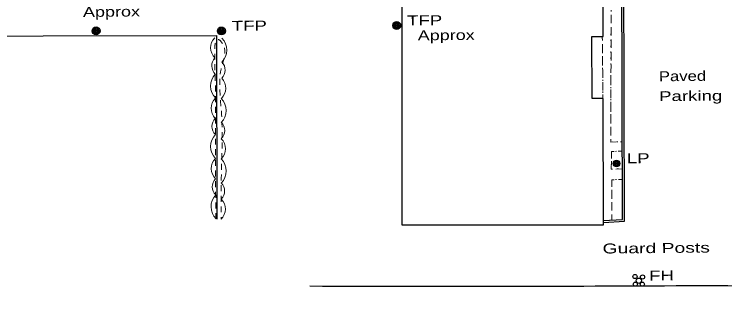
# Model space of a CAD drawing. Extents: x 2362213 to 2366494, y 6968794 to 6978110.
# Drawn here: x 2363722.2 to 2364064.6, y 6975816.2 to 6975952.7 of the extents above; entities that cross this region are included whole.
import ezdxf

# ---------------------------------------------------------------- set-up
doc = ezdxf.new("R2010")
doc.units = 0
doc.header["$LTSCALE"] = 1.9
for name, pattern in [('DASH_DOUBLE_DOT', [9.2, 5, -1.2, 0.3, -1.2, 0.3, -1.2]), ('DOTTED', [1.5, 0.3, -1.2]), ('SHORT_DASHED', [2.7, 1.5, -1.2])]:
    doc.linetypes.add(name, pattern=pattern)
for name, color, linetype, lineweight in [('11', 7, 'Continuous', 25), ('13', 7, 'Continuous', 13), ('2', 7, 'Continuous', 25), ('20', 7, 'Continuous', 25), ('25', 7, 'Continuous', 25), ('29', 7, 'Continuous', 13), ('35', 7, 'Continuous', 13), ('7', 7, 'Continuous', 25)]:
    doc.layers.add(name, color=color, linetype=linetype, lineweight=lineweight)

msp = doc.modelspace()

# ---------------------------------------------------------------- linework, layer by layer
at = {"layer": '11'}
msp.add_lwpolyline([(2364005.429, 6976091.845), (2363908.886, 6976091.766), (2363909.079, 6975850.977), (2364006.102, 6975851.05), (2364006.053, 6975911.893), (2364000.643, 6975911.891), (2364000.637, 6975941.923), (2364005.977, 6975941.923), (2364005.966, 6976001.926), (2364000.315, 6976001.922), (2364000.291, 6976031.843), (2364005.441, 6976031.842)], close=True, dxfattribs=at)
msp.add_lwpolyline([(2363569.083, 6975884.661), (2363568.867, 6975941.911), (2363819.655, 6975942.339), (2363819.848, 6975853.777)], dxfattribs=at)
at = {"layer": '13'}
for p, q in [((2364009.808, 6975952.36), (2364009.806, 6975948.36)), ((2364009.805, 6975946.36), (2364009.803, 6975942.36)), ((2364005.636, 6975939.89), (2364005.607, 6975941.92)), ((2364009.802, 6975940.36), (2364009.8, 6975936.36)), ((2364005.694, 6975933.89), (2364005.655, 6975937.89)), ((2364009.799, 6975934.359), (2364009.797, 6975930.359)), ((2364005.761, 6975927.891), (2364005.713, 6975931.89)), ((2364009.796, 6975928.359), (2364009.794, 6975924.359)), ((2364005.828, 6975921.891), (2364005.78, 6975925.891)), ((2364005.885, 6975915.891), (2364005.847, 6975919.891)), ((2364009.794, 6975922.359), (2364009.782, 6975918.359)), ((2364009.781, 6975916.358), (2364009.769, 6975912.358)), ((2364005.923, 6975911.892), (2364005.904, 6975913.891)), ((2364009.768, 6975910.358), (2364009.756, 6975906.358)), ((2364009.755, 6975904.357), (2364009.753, 6975900.357)), ((2364009.752, 6975898.357), (2364009.74, 6975894.357)), ((2364014.323, 6975891.061), (2364015.303, 6975891.09)), ((2364015.316, 6975886.57), (2364013.316, 6975886.491)), ((2364012.108, 6975877.909), (2364015.337, 6975878.01)), ((2364015.356, 6975872.9), (2364013.356, 6975872.831)), ((2364010.202, 6975867.89), (2364010.22, 6975863.89)), ((2364010.229, 6975861.89), (2364010.237, 6975857.889)), ((2364010.246, 6975855.89), (2364010.251, 6975853.32))]:
    msp.add_line(p, q, dxfattribs=at)
at = {"layer": '13', "linetype": 'DOTTED'}
msp.add_line((2364005.923, 6975911.892), (2364005.607, 6975941.92), dxfattribs=at)
for points in [[(2364015.087, 6975963.101), (2364009.816, 6975963.091), (2364009.733, 6975890.947), (2364015.303, 6975891.09)], [(2364015.316, 6975886.57), (2364010.006, 6975886.359), (2364009.937, 6975877.838), (2364015.337, 6975878.01)], [(2364015.356, 6975872.9), (2364010.186, 6975872.72), (2364010.251, 6975853.32)]]:
    msp.add_lwpolyline(points, dxfattribs=at)
at = {"layer": '13'}
for points in [[(2364009.739, 6975892.357), (2364009.733, 6975890.947), (2364012.323, 6975891.012)], [(2364011.317, 6975886.412), (2364010.006, 6975886.359), (2364009.982, 6975883.669)], [(2364009.971, 6975881.668), (2364009.937, 6975877.838), (2364010.107, 6975877.84)], [(2364011.357, 6975872.762), (2364010.186, 6975872.72), (2364010.193, 6975869.89)]]:
    msp.add_lwpolyline(points, dxfattribs=at)
at = {"layer": '2'}
for points in [[(2364006.053, 6975853.1), (2364015.41, 6975853.579), (2364014.702, 6976094.903)], [(2364006.102, 6975852.141), (2364016.368, 6975852.668), (2364015.662, 6976094.903)]]:
    msp.add_lwpolyline(points, dxfattribs=at)
msp.add_spline([(2364107.921, 6975821.279), (2364052.236, 6975821.458), (2363963.325, 6975821.152), (2363864.629, 6975821.302)], degree=3, dxfattribs=at)
at = {"layer": '20'}
for centre, radius in [((2363906.543, 6975947.187), 1.9), ((2363906.543, 6975947.187), 1.442), ((2363906.543, 6975947.187), 0.973), ((2363906.543, 6975947.187), 0.539), ((2363906.543, 6975947.187), 0.192), ((2363761.69, 6975944.607), 1.9), ((2363761.69, 6975944.607), 1.442), ((2363761.69, 6975944.607), 0.973), ((2363761.69, 6975944.607), 0.539), ((2363761.69, 6975944.607), 0.192), ((2363822.073, 6975944.572), 1.9), ((2363822.073, 6975944.572), 1.442), ((2363822.073, 6975944.572), 0.973), ((2363822.073, 6975944.572), 0.539), ((2363822.073, 6975944.572), 0.192), ((2364012.451, 6975880.632), 1.6), ((2364012.451, 6975880.632), 1.3), ((2364012.451, 6975880.632), 1), ((2364012.451, 6975880.632), 0.539), ((2364012.451, 6975880.632), 0.192), ((2364023.201, 6975824.002), 1.3)]:
    msp.add_circle(centre, radius, dxfattribs=at)
at = {"layer": '25', "linetype": 'DASH_DOUBLE_DOT'}
msp.add_spline([(2364310.491, 6975656.319), (2364309.315, 6975672.72), (2364298.364, 6975726.467), (2364286.692, 6975764.268), (2364256.739, 6975841.117), (2364237.482, 6975880.675), (2364207.194, 6975936.919), (2364187.287, 6975969.191), (2364152.962, 6976013.656), (2364115.828, 6976058.935), (2364082.642, 6976102.511), (2364057.611, 6976141.394), (2364041.755, 6976162.894), (2364026.344, 6976185.928), (2364018.13, 6976197.872), (2364016.1, 6976205.372), (2364015.847, 6976210.94), (2364013.084, 6976216.455), (2364009.051, 6976219.846), (2363997.967, 6976222.231), (2363988.629, 6976226.282), (2363979.044, 6976231.97), (2363962.438, 6976249.274), (2363954.619, 6976263.83), (2363947.844, 6976280.085), (2363938.606, 6976306.129), (2363935.221, 6976325.478), (2363933.103, 6976340.059), (2363930.105, 6976355.511)], degree=3, dxfattribs=at)
at = {"layer": '29'}
for centre, radius, start, end in [((2363823.781, 6975936.474), 6.886, 135.85646, 225.85646), ((2363816.433, 6975935.315), 8.259, 314.79119, 44.79119), ((2363822.939, 6975927.676), 5.503, 135.85646, 225.85646), ((2363818.369, 6975925.678), 5.503, 314.33041, 44.33041), ((2363825.088, 6975918.025), 8.259, 135.66055, 225.66055), ((2363817.292, 6975916.896), 6.886, 314.44237, 44.44237), ((2363824.023, 6975907.24), 6.886, 134.96599, 224.96599), ((2363816.127, 6975906.143), 8.259, 314.92396, 44.92396), ((2363823.047, 6975898.465), 5.503, 135.10415, 225.10415), ((2363818.149, 6975896.479), 5.503, 314.92396, 44.92396), ((2363825.1, 6975888.808), 8.259, 135.10415, 225.10415), ((2363817.169, 6975887.685), 6.886, 315.05243, 45.05243), ((2363824.081, 6975878.122), 6.886, 135.45874, 225.45874), ((2363816.117, 6975876.97), 8.259, 315.05243, 45.05243), ((2363823.177, 6975869.33), 5.503, 135.45874, 225.45874), ((2363818.131, 6975867.33), 5.503, 314.76754, 44.76754), ((2363825.326, 6975859.712), 8.259, 135.71437, 225.71437), ((2363817.115, 6975858.555), 6.886, 314.69263, 44.69263)]:
    msp.add_arc(centre, radius, start, end, dxfattribs=at)
at = {"layer": '29', "linetype": 'SHORT_DASHED'}
msp.add_spline([(2363819.488, 6975853.794), (2363819.201, 6975881.791), (2363819.179, 6975917.704), (2363818.93, 6975936.542), (2363819.482, 6975939.447), (2363820.264, 6975940.335), (2363822.358, 6975938.895), (2363822.266, 6975927.483), (2363822.039, 6975906.23), (2363822.032, 6975873.339), (2363821.939, 6975853.667)], degree=3, dxfattribs=at)
at = {"layer": '35'}
for points in [[(2363990.406, 6976188.806), (2363992.575, 6976186.897), (2363996.452, 6976182.874), (2364003.212, 6976175.529), (2364007.446, 6976171.019), (2364010.63, 6976168.578), (2364016.009, 6976162.359), (2364019.42, 6976159.021), (2364022.007, 6976158.347), (2364024.56, 6976158.051), (2364026.089, 6976158.146), (2364027.367, 6976158.318), (2364029.458, 6976158.248), (2364032.551, 6976157.067), (2364036.88, 6976152.938), (2364042.836, 6976145.964), (2364049.226, 6976136.564), (2364054.441, 6976129.744), (2364062.778, 6976118.602), (2364068.922, 6976107.631), (2364074.796, 6976097.796), (2364079.901, 6976090.004), (2364084.92, 6976082.863), (2364092.481, 6976072.123), (2364099.555, 6976063.501), (2364117.192, 6976043.787), (2364122.493, 6976034.397), (2364126.085, 6976025.801), (2364137.228, 6976008.626), (2364147.201, 6975992.69), (2364155.168, 6975982.586), (2364163.136, 6975977.462), (2364172.666, 6975966.002), (2364178.411, 6975959.226), (2364180.991, 6975951.9), (2364184.396, 6975943.892), (2364186.692, 6975937.054), (2364188.392, 6975930.79), (2364188.505, 6975925.261), (2364188.357, 6975918.779), (2364187.038, 6975915.346), (2364188.252, 6975908.788), (2364188.827, 6975900.903), (2364187.715, 6975892.742), (2364185.545, 6975886.321), (2364182.16, 6975881.697), (2364178.232, 6975878.241), (2364173.628, 6975875.467), (2364168.822, 6975873.971), (2364164.374, 6975871.619), (2364159.073, 6975870.748), (2364154.895, 6975870.518), (2364149.335, 6975870.495)], [(2363986.475, 6976185.679), (2363988.471, 6976183.058), (2363997.525, 6976170.994), (2364006.103, 6976158.674), (2364021.423, 6976142.98), (2364030.11, 6976131.853), (2364044.938, 6976113.192), (2364055.919, 6976100.676), (2364070.484, 6976081.144), (2364086.205, 6976061.314), (2364096.959, 6976049.215), (2364111.854, 6976028.816), (2364122.774, 6976014.319), (2364134.684, 6975998.622), (2364146.432, 6975984.213), (2364155.059, 6975970.854), (2364160.013, 6975961.981), (2364165.438, 6975952.102), (2364166.38, 6975943.531), (2364166.462, 6975935.971), (2364165.017, 6975924.847), (2364162.383, 6975917.902), (2364160.68, 6975916.055), (2364158.427, 6975915.454), (2364157.105, 6975915.631), (2364155.096, 6975917.612)]]:
    msp.add_spline(points, degree=3, dxfattribs=at)
at = {"layer": '7'}
for centre in [(2364021.342, 6975826.004), (2364025.004, 6975825.769), (2364021.517, 6975822.316), (2364024.897, 6975822.318)]:
    msp.add_circle(centre, 1, dxfattribs=at)

# ---------------------------------------------------------------- texts
at = {"layer": '2'}
for s, width, p in [('Paved', 1.25, (2364032.895, 6975920.269)), ('Parking', 1.4, (2364032.987, 6975910.669))]:
    msp.add_text(s, height=4.8, rotation=0.546, dxfattribs=dict(at, width=width)).set_placement(p)
at = {"layer": '20'}
for s, width, p in [('Approx', 1.35, (2363755.406, 6975951.328)), ('  TFP', 1.4, (2363906.542, 6975947.187)), ('  TFP', 1.4, (2363822.073, 6975944.572)), ('Approx', 1.35, (2363916.681, 6975940.023)), ('  LP', 1.4, (2364012.452, 6975880.631)), ('  FH', 1.4, (2364023.191, 6975823.992))]:
    msp.add_text(s, height=4.8, rotation=0.546, dxfattribs=dict(at, width=width)).set_placement(p)
at = {"layer": '7', "width": 1.45}
msp.add_text('Guard Posts', height=4.8, rotation=0.546, dxfattribs=at).set_placement((2364005.745, 6975837.115))

doc.saveas('drawing.dxf')
